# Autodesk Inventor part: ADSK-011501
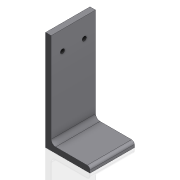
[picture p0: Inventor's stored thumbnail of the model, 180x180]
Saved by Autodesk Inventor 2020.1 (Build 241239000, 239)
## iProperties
Created: 2000-02
Part Number: ADSK-011501
Material: RA HRS
Document SubType Name: Modeling
Designer: sspink
Density: 7.83 g/cm^3
Appearance: Métal - Acier
Mass: 400.425 g
Surface Area: 187.373 cm^2
Volume: 51.1399 cm^3
Control State: 0
Checked Out: False
Master: False
Shininess: 0.0
Length Units: 11269
Angle Units: 11279
Time Units: 11290
Mass Units: 11283
Length Display Precision: 3
Angle Display Precision: 2
Compacted: True
Cutlength: 2
Material Desc: ANGLE,HRS,0.25 X 5.00 X 3.00
Material_number: A084067
Dimensions: 50,8x114,3x50,8 mm
Mass: 0,4 kg
DocNumber: ADSK-011501.ipt
Folder: 01 - Themengebiete\Simplification\01 - Packaging machine\
VDS_Category: 3D Komponenten
Density: 0.0
Volumn: 0.0
Area: 0.0
PropertySet Name: Model Information
Author: sspink
Revision Number: -
Title: profile
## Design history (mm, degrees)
node "Element2:1"
node "Extrusion1" dims "d9" = 25.4, "d10" = 0
node "Hole2" dims "d20" = 4.917, "d21" = 9.525, "d22" = 6.35, "d23" = 60 deg, "d24" = 17.1, "d25" = 118 deg, "d27" = 12
  sketch "Sketch4"
    geometry: L1 (50.8, 114.3)-(0, 114.3) reference; L2 (37.9, 92.3)-(12.9, 92.3); 2 further points
    constraints: 2 end point, 2 midpoint, 1 horizontal, 1 horizontal alignment, 1 vertical alignment
    dimensions: "d11" = 22 distance from line of L2.start L1; "d26" = 25 distance of L2.start L2.end
node "Solide1"
node "Corps solides"
node "Corps surfaciques"
sketch "Sketch2"
  geometry: L1 (32.408, 38.758)-(83.208, 38.758); L2 (32.408, 165.758)-(32.408, 38.758); L3 (38.758, 162.583)-(38.758, 50.188); L4 (43.838, 45.108)-(80.033, 45.108); L5 (32.408, 165.758)-(35.583, 165.758); L6 (83.208, 41.933)-(83.208, 38.758); A1 r 3.175 centre (35.583, 162.583) between (38.758, 162.583) and (35.583, 165.758); A2 r 3.175 centre (80.033, 41.933) between (83.208, 41.933) and (80.033, 45.108); A3 r 5.08 centre (43.838, 50.188) between (38.758, 50.188) and (43.838, 45.108); 1 further point
  constraints: 12 end point, 6 point on circle, 6 tangent, 3 centre point, 1 coincident, 1 equal radius, 1 horizontal, 1 perpendicular, 1 other
  dimensions: "d0" = 6.35 distance between parallel lines of L2 L3 (derived); "d3" = 3.175 radius of A1 (derived); "d4" = 5.08 radius of A3 (derived); "d1" = 127 distance between parallel lines of L1 L5 (derived); "d2" = 50.8 distance between parallel lines of L6 L2 (derived)
sketch "Sketch3"
  geometry: L1 (50.8, 127)-(50.8, 0) reference; L2 (47.625, 127)-(50.8, 127) reference; L3 (44.45, 11.43)-(44.45, 123.825) reference; L4 (44.45, 114.3)-(50.8, 114.3); A1 r 3.175 centre (47.625, 123.825) between (47.625, 127) and (44.45, 123.825) reference
  constraints: 2 end point, 2 point on line, 1 perpendicular
  dimensions: "d8" = 12.7 distance between parallel lines of L2 L4
